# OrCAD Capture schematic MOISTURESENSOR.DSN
size A; title: Moisture Sensor Schematic
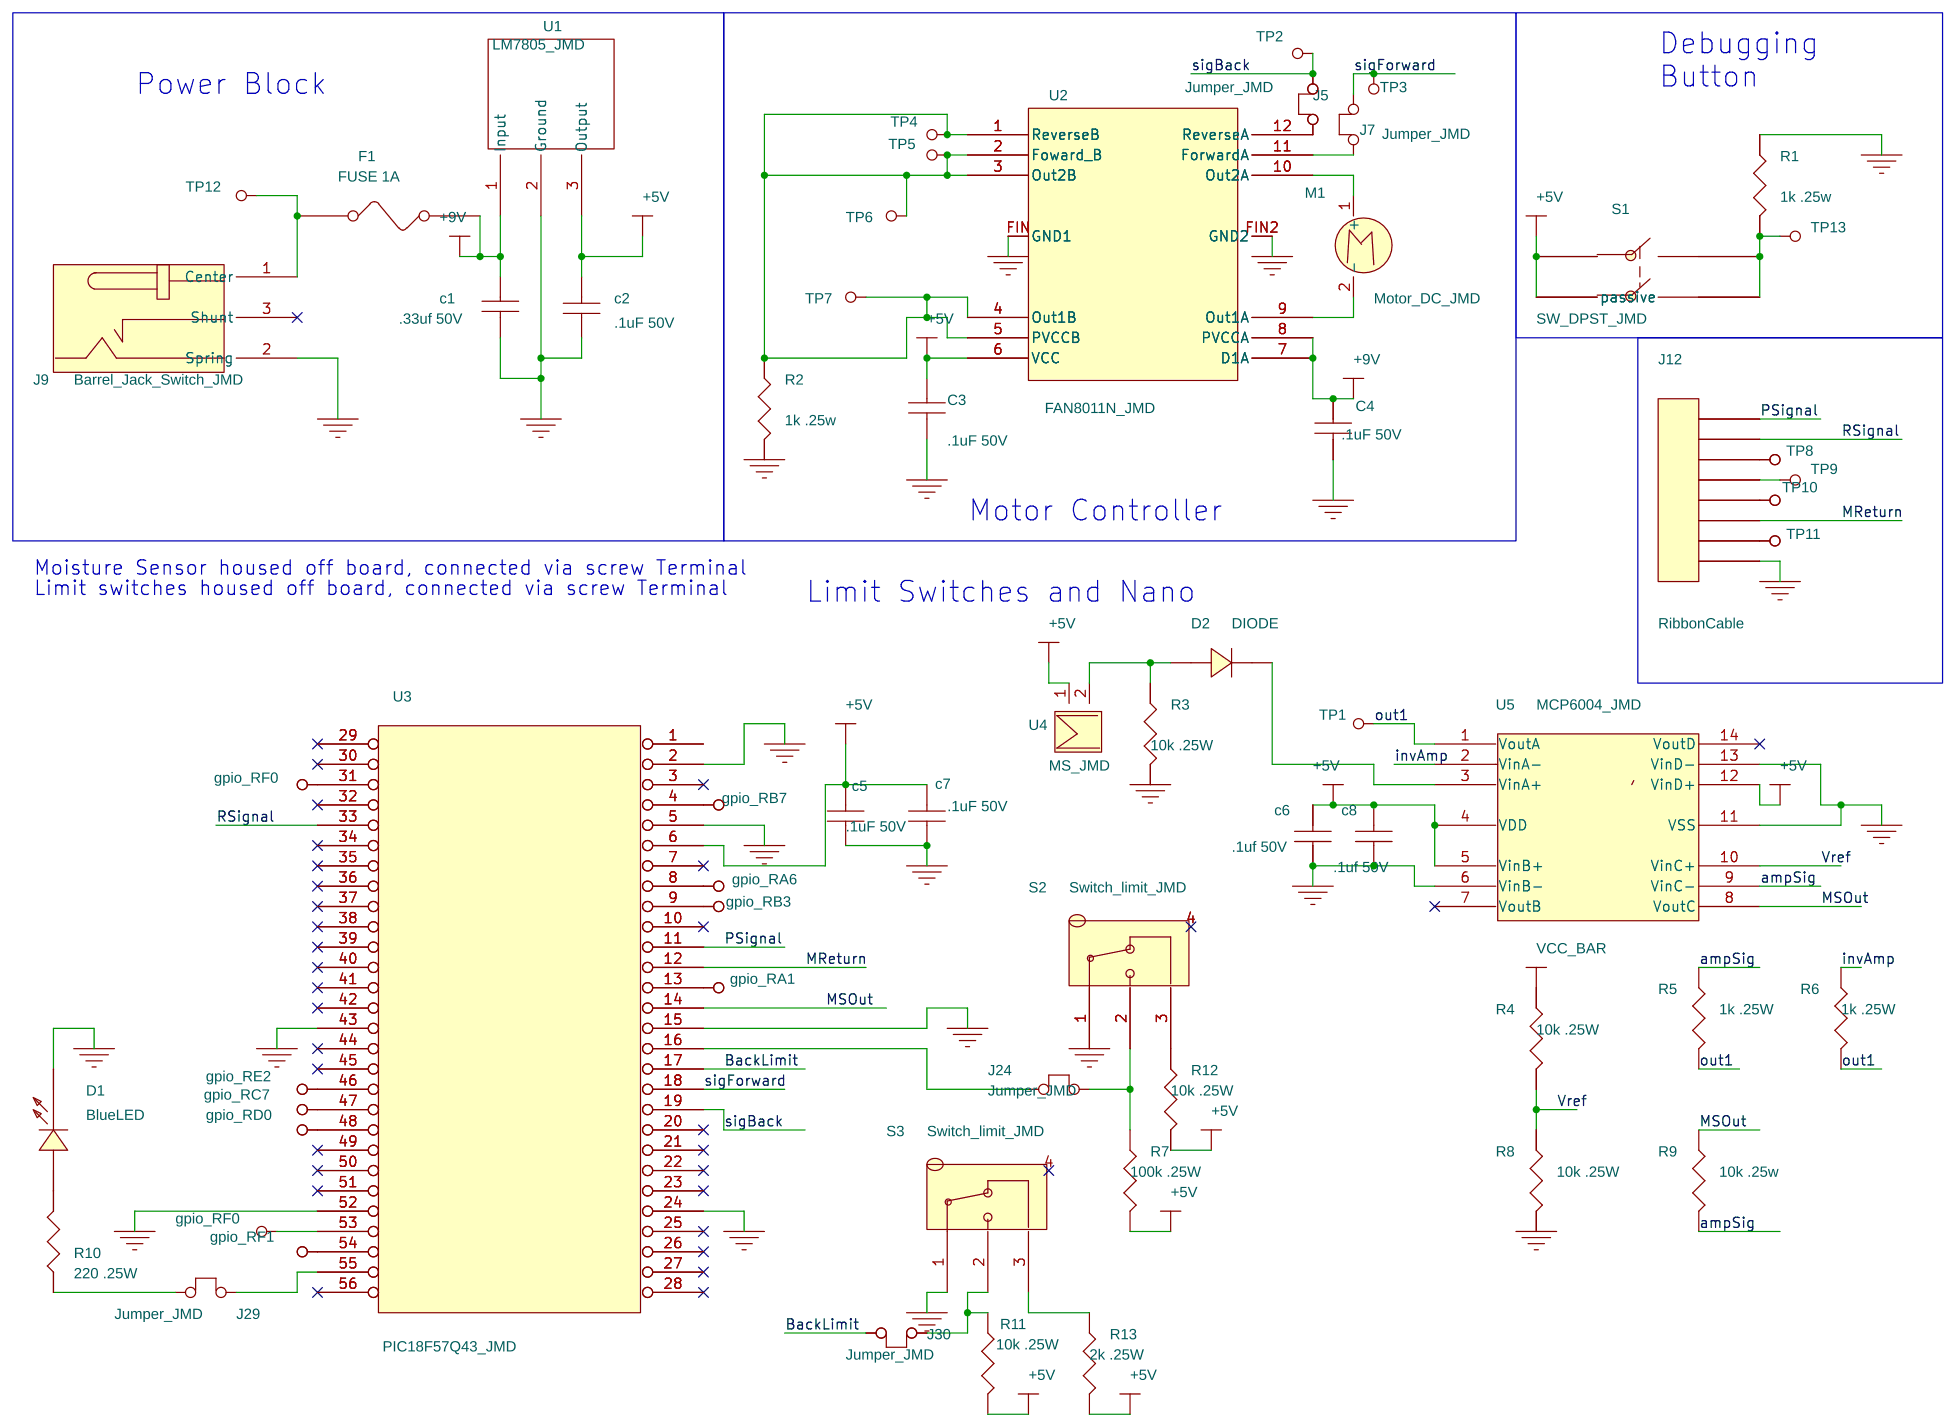
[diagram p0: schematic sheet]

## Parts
c1  .33uf 50V  [capacitor]
c2  .1uF 50V  [capacitor]
C3  .1uF 50V  [capacitor]
C4  .1uF 50V  [capacitor]
c5  .1uF 50V  [capacitor]
c6  .1uf 50V  [capacitor]
c7  .1uF 50V  [capacitor]
c8  .1uf 50V  [capacitor]
D1  BlueLED  [capacitor]
D2  DIODE  [capacitor]
F1  FUSE 1A  [fuseHolder]
J1  TP2  [MalePinHole]
J2  TP3  [MalePinHole]
J3  TP5  [MalePinHole]
J4  TP12  [MalePinHole]
J5  Jumper_JMD  [jumper]
J6  TP4  [MalePinHole]
J7  Jumper_JMD  [jumper]
J8  TP6  [MalePinHole]
J9  Barrel_Jack_Switch_JMD  [BarrelJackdevelopers_JMD]
J10  TP13  [MalePinHole]
J11  TP7  [MalePinHole]
J12  RibbonCable  [DIP8Pin]
J13  TP8  [MalePinHole]
J14  TP9  [MalePinHole]
J15  TP10  [MalePinHole]
J16  TP11  [MalePinHole]
J17  gpio_RF0  [MalePinHole]
J18  TP1  [MalePinHole]
J19  gpio_RB7  [malePinHole]
J20  gpio_RA6  [MalePinHole]
J21  gpio_RB3  [MalePinHole]
J22  gpio_RA1  [MalePinHole]
J23  gpio_RE2  [MalePinHole]
J24  Jumper_JMD  [jumper]
J25  gpio_RC7  [MalePinHole]
J26  gpio_RD0  [MalePinHole]
J27  gpio_RF0  [MalePinHole]
J28  gpio_RF1  [MalePinHole]
J29  Jumper_JMD  [capacitor]
J30  Jumper_JMD  [jumper]
M1  Motor_DC_JMD  [screwTerminal]
R1  1k .25w  [Resistor_intro]
R2  1k .25w  [Resistor_intro]
R3  10k .25W  [Resistor_intro]
R4  10k .25W  [Resistor_intro]
R5  1k .25W  [Resistor_intro]
R6  1k .25W  [Resistor_intro]
R7  100k .25W  [Resistor_intro]
R8  10k .25W  [Resistor_intro]
R9  10k .25w  [Resistor_intro]
R10  220 .25W  [Resistor_intro]
R11  10k .25W  [Resistor_intro]
R12  10k .25W  [Resistor_intro]
R13  2k .25W  [Resistor_intro]
S1  SW_DPST_JMD  [sw_dpst]
S2  Switch_limit_JMD  [LimitSwitch]
S3  Switch_limit_JMD  [LimitSwitch]
U1  LM7805_JMD  [LinearVoltReg]
U2  FAN8011N_JMD  [hBridgeWithFin]
U3  PIC18F57Q43_JMD  [Microchip_PIC18F57Q43]
U4  MS_JMD  [screwTerminal]
U5  MCP6004_JMD  [opampjmd]

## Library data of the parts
c1 c2 C3 C4 c5-c8 = CAPACITOR_NON-POL
D1 = LED
D2 = DIODE
F1 = FUSE
J1-J4 J6 J10 J13-J17 J20-J23 J25-J28 = MalePinPlaceHolder_JMD
J5 J7 J24 J29 J30 = jumper_jmd
J8 = malePinPlaceHolderOutput_JMD_0
J9 = Barrel_Jack_Switch_JMD
J11 = malePinPlaceHolderOutput_JMD_1
J12 = CONN_TRBLK_8
J18 = MalePinPlaceHolder_JMD_6
J19 = malePinPlaceHolderOutput_JMD
M1 = Motor_DC_JMD
R1-R13 = RESISTOR
S1 = SW_DPST_JMD
S2 S3 = 463093691402_Limit_JMD
U1 = LM7805_JMD_0
U2 = FAN8011N_JMD_2
U3 = PIC18F57Q43_JMD
U4 = MoistureSenosr_JMD
U5 = MCP6004_JMD

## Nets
+5V: c2.2 C3.1 c5.2 c6.2 c7.2 c8.2 R4.1 R7.2 R11.2 R12.2 R13.2 S1.1(passive) S1.3 U1.3(Output) U2.6(VCC) U3.6(VTG) U4.1 U5.4(VDD) U5.5(VinB+) U5.12(VinD+)
+9V: c1.1 C4.1 F1.2 U1.1(Input) U2.7(D1A) U2.8(PVCCA)
GND: c1.2 c2.1 C3.2 C4.2 c5.1 c6.1 c7.1 c8.1 D1.1(CATHODE) J9.2(Spring) J12.8 R1.1 R2.2 R3.2 R8.2 S2.1(COM) S3.1(COM) U1.2(Ground) U2.FIN(GND1) U2.FIN2(GND2) U3.2(VOFF) U3.5(GND1) U3.15(GND2) U3.24(GND3) U3.43(GND4) U3.52(GND5) U5.6(VinB-) U5.11(VSS) U5.13(VinD-)
VBUS: U3.1(Vbus)
ampSig: R5.1 R9.2 U5.9(VinC-)
BackLimit: J30.1 U3.17(RD6)
invAmp: R6.1 U5.2(VinA-)
MReturn: J12.6 U3.12(RA2)
MSOut: R9.1 U3.14(RA0) U5.8(VoutC)
out1: J18.1(port) R5.2 R6.2 U5.1(VoutA)
PSignal: J12.1 U3.11(RB0)
RSignal: J12.2 U3.33(RB6)
sigBack: J1.1(port) J5.1 U3.19(RB5)
sigForward: J2.1(port) J7.1 U3.18(RD5)
Vref: R4.2 R8.1 U5.10(VinC+)
N91840: J3.1(port) J6.1(port) J8.1 J11.1 R2.1 U2.1(ReverseB) U2.2(Foward_B) U2.3(Out2B) U2.4(Out1B) U2.5(PVCCB)
N91848: J7.2 U2.11(ForwardA)
N91894: M1.1(+) U2.10(Out2A)
N91902: F1.1 J4.1(port) J9.1(Center)
N92202: M1.2(-) U2.9(Out1A)
N93412: J24.2 U3.16(RD7)
N93642: J27.1(port) U3.53(RF0)
N93710: J29.1 U3.55(RF2)
N93718: J29.2 R10.1
N93780: J30.2 R11.1 S3.2(NO)
N93800: R13.1 S3.3(NC)
N113659: J10.1(port) R1.2 S1.2 S1.4
N116351: J24.1 R7.1 S2.2(NO)
N125765: D2.2(A) R3.1 U4.2
N125778: D2.1(K) U5.3(VinA+)
N129031: J12.4 J14.1(port)
N139610: J12.5 J15.1(port)
N139611: J12.7 J16.1(port)
N139612: J20.1(port) U3.8(RA6)
N139613: J12.3 J13.1(port)
N139614: J17.1(port) U3.31(RF0U)
N139615: D1.2(ANODE) R10.2
N139616: J28.1(port) U3.54(RF1)
N139617: J21.1(port) U3.9(RA5)
N139619: J22.1(port) U3.13(RA1)
N139620: J26.1(port) U3.48(RD0)
N139621: J25.1(port) U3.47(RC7)
N139622: J19.1 U3.4(RB7)
N139624: J23.1(port) U3.46(RE2)
N139625: J5.2 U2.12(ReverseA)
N142168: R12.1 S2.3(NC)

Not connected (* = marked no-connect by the designer): J9 3(Shunt)*; S2 4(null)*; S3 4(null)*; U3 3(RE3)* 7(RA7)* 10(RB3)* 20(RF7)* 21(RF6)* 22(RF5)* 23(RF4)* 25(RE1)* 26(RE0)* 27(RC1)* 28(RC0)* 29(NC)* 30(ID)* 32(RF1U)* 34(RB4)* 35(RC2)* 36(RC3)* 37(RB2)* 38(RB1)* 39(RC4)* 40(RC5)* 41(RC6)* 42(RD4)* 44(RA3)* 45(RA4)* 49(RD1)* 50(RD2)* 51(RD3)* 56(RF3)*; U5 7(VoutB)* 14(VoutD)*

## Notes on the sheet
- Debugging
  Button
- Power Block
- Motor Controller
- Moisture Sensor housed off board, connected via screw Terminal
- Limit switches housed off board, connected via screw Terminal
- Limit Switches and Nano
